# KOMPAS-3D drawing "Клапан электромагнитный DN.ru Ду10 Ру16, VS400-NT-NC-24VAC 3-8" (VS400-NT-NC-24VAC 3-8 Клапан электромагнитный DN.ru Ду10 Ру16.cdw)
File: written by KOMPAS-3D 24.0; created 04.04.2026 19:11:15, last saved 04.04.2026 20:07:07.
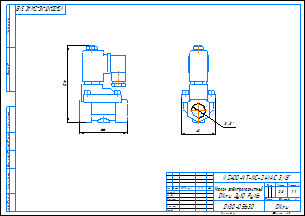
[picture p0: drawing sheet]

Document properties: c3d_UniqueCompID: ef56311e-7521-43dc-8291-0e6108b3d81d; Обозначение: VS400-ET-NC-220VAC 3-8; Наименование: Клапан электромагнитный DN.ru Ду10 Ру16; Автор: artio; Класс точности: c; Знак неуказанной шероховатости: Шероховатость не задана; Рассекать на разрезах: Да; Автор: artio; Форматы листов документа: A3; Полное имя файла: VS400-NT-NC-24VAC 3-8 Клапан электромагнитный DN.ru Ду10 Ру16.m3d; Масса: 0.797; Наименование: Клапан электромагнитный DN.ru Ду10 Ру16; Количество листов документа: 1; Примечание: D130-05630

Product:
- Body: Тело 1  | qty 1
    Масса: 1.030062
- Part/product: Клапан электромагнитный DN.ru Ду10 Ру16  | designation VS400-NT-NC-24VAC 3-8
    Масса: 0.797
    Раздел спецификации: Прочие изделия
    Примечание: D130-05630
    additional columns: ef56311e-7521-43dc-8291-0e6108b3d81d; VS400-ET-NC-220VAC 3-8; artio; c; Шероховатость не задана; Да

Views: Вид 1, Спереди, Проекционный вид 2
Referenced files in C:\Users\artio\OneDrive\Рабочий стол\Клапан электромагнитный DN.ru\VS400-ET-NC\VS400-ET-NC-24VDC\: VS400-ET-NC-24VDC 3-8 Клапан электромагнитный DN.ru Ду10 Ру16.m3d
Referenced files in C:\Users\artio\OneDrive\Рабочий стол\Клапан электромагнитный DN.ru\VS400-NT-NC\VS400-NT-NC-24VAC\: VS400-NT-NC-24VAC 3-8 Клапан электромагнитный DN.ru Ду10 Ру16.m3d
Referenced files in C:\Users\artio\OneDrive\Рабочий стол\Клапан электромагнитный DN.ru\VS400-ET-NC\: VS400-ET-NC-24VDC 3-8 Клапан электромагнитный DN.ru Ду10 Ру16.cdw
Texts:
  VS400-NT-NC-24VAC 3-8
  Клапан электромагнитный
  DN.ru Ду10 Ру16
  VS400-NT-NC-24VAC 3/8"
  VS400-NT-NC-24VAC 3/8"-
  Клапан электромагнитный DN.ru Ду10 Ру16
  VS400-NT-NC-24VAC 3-8 Клапан электромагнитный DN.ru Ду10 Ру16
Dimensions and other numbers on the sheet: 0; 3; 2; 4; 48; 3/8"; 66; 106; 1:1; 1; 0,8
